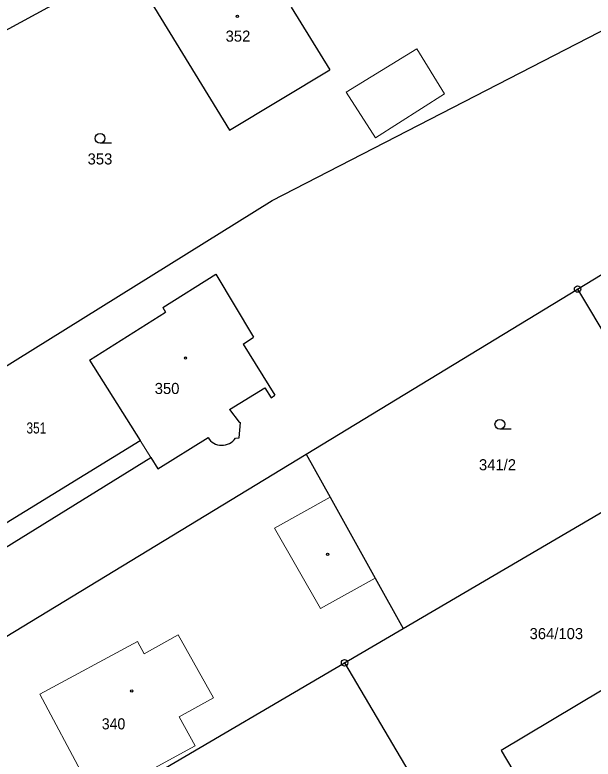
# Model space of a CAD drawing. Extents: x -592965 to -592390, y -1145071 to -1144631.
# Drawn here: x -592638.4 to -592594.1, y -1144937.6 to -1144880.5 of the extents above; entities that cross this region are included whole.
import ezdxf

# ---------------------------------------------------------------- set-up
doc = ezdxf.new("R2010")
doc.units = 0
doc.header["$LTSCALE"] = 0.17
doc.layers.add('4', color=7, linetype='Continuous', lineweight=25)

msp = doc.modelspace()

# ---------------------------------------------------------------- linework, layer by layer
at = {"layer": '4'}
for p, q in [((-592618.69, -1144894.73), (-592582.6, -1144876.15)), ((-592628.45, -1144878.77), (-592621.96, -1144889.35)), ((-592639.79, -1144882.02), (-592635.02, -1144879.44)), ((-592617.24, -1144879.9), (-592614.27, -1144884.71)), ((-592621.96, -1144889.35), (-592614.27, -1144884.71)), ((-592631.025, -1144890.34), (-592631.9, -1144890.34)), ((-592641.03, -1144908.63), (-592618.69, -1144894.73)), ((-592627.1, -1144902.94), (-592623.01, -1144900.39)), ((-592623.01, -1144900.39), (-592620.12, -1144905.2)), ((-592595.26, -1144901.52), (-592587.26, -1144915.04)), ((-592632.71, -1144906.97), (-592626.88, -1144903.29)), ((-592627.1, -1144902.94), (-592626.88, -1144903.29)), ((-592620.93, -1144905.75), (-592620.12, -1144905.2)), ((-592620.93, -1144905.75), (-592618.49, -1144909.67)), ((-592632.71, -1144906.97), (-592628.83, -1144913.14)), ((-592621.97, -1144910.75), (-592619.25, -1144909.11)), ((-592621.97, -1144910.75), (-592621.22, -1144911.74)), ((-592621.22, -1144911.74), (-592621.12, -1144911.75)), ((-592600.355, -1144912.27), (-592601.23, -1144912.27)), ((-592627.47, -1144915.3), (-592623.62, -1144912.91)), ((-592642.54, -1144921.54), (-592628.83, -1144913.14)), ((-592643.64, -1144930.93), (-592616.08, -1144914.18)), ((-592642.78, -1144923.56), (-592628, -1144914.45)), ((-592628, -1144914.45), (-592627.47, -1144915.3)), ((-592616.08, -1144914.18), (-592614.24, -1144917.49)), ((-592614.24, -1144917.49), (-592610.8, -1144923.69)), ((-592613.14, -1144930.18), (-592608.64, -1144927.55)), ((-592636.52, -1144943.86), (-592613.14, -1144930.18))]:
    msp.add_line(p, q, dxfattribs=at)
at = {"layer": '4', "lineweight": 13}
for p, q in [((-592613.01, -1144886.42), (-592607.59, -1144883.1)), ((-592607.59, -1144883.1), (-592605.47, -1144886.56)), ((-592613.01, -1144886.42), (-592610.78, -1144889.93)), ((-592610.78, -1144889.93), (-592605.47, -1144886.56)), ((-592628.83, -1144913.14), (-592628, -1144914.45)), ((-592618.53, -1144919.87), (-592614.24, -1144917.49)), ((-592618.53, -1144919.87), (-592614.99, -1144926.02)), ((-592614.99, -1144926.02), (-592610.8, -1144923.69)), ((-592636.53, -1144932.59), (-592629.03, -1144928.56)), ((-592629.03, -1144928.56), (-592628.51, -1144929.49)), ((-592636.53, -1144932.59), (-592632.22, -1144940.68)), ((-592625.83, -1144934.33), (-592623.21, -1144932.88)), ((-592625.83, -1144934.33), (-592624.61, -1144936.54)), ((-592632.22, -1144940.68), (-592624.61, -1144936.54))]:
    msp.add_line(p, q, dxfattribs=at)
at = {"layer": '4'}
for points in [[(-592616.08, -1144914.18), (-592595.26, -1144901.52), (-592574.92, -1144889.15)], [(-592619.25, -1144909.11), (-592618.77, -1144909.86), (-592618.49, -1144909.67)], [(-592621.52, -1144912.95), (-592621.24, -1144912.94), (-592621.12, -1144911.75)], [(-592610.8, -1144923.69), (-592608.64, -1144927.55), (-592588.13, -1144915.55)], [(-592613.14, -1144930.18), (-592597.16, -1144957.25), (-592596.1, -1144959.04)]]:
    msp.add_lwpolyline(points, dxfattribs=at)
msp.add_lwpolyline([(-592601.13, -1144936.9), (-592597.88, -1144942.39), (-592595.3, -1144940.9), (-592592.02, -1144946.46), (-592584.34, -1144941.94), (-592587.57, -1144936.44), (-592582.29, -1144933.34), (-592585.64, -1144927.65)], close=True, dxfattribs=at)
at = {"layer": '4', "lineweight": 13}
msp.add_lwpolyline([(-592628.51, -1144929.49), (-592625.91, -1144928.03), (-592623.21, -1144932.88)], dxfattribs=at)
at = {"layer": '4'}
for centre, radius in [((-592621.37, -1144880.61), 0.0875), ((-592631.9, -1144889.965), 0.375), ((-592595.26, -1144901.52), 0.25), ((-592595.26, -1144901.52), 0.0164), ((-592625.35, -1144906.81), 0.0875), ((-592601.23, -1144911.895), 0.375), ((-592614.45, -1144921.87), 0.0875), ((-592613.14, -1144930.18), 0.25), ((-592613.14, -1144930.18), 0.0164), ((-592629.47, -1144932.34), 0.0875)]:
    msp.add_circle(centre, radius, dxfattribs=at)
msp.add_arc((-592622.5572, -1144912.2595), 1.2461, 211.47165, 326.34592, dxfattribs=at)

# ---------------------------------------------------------------- texts
for s, p in [('352', (-592622.27, -1144882.55)), ('353', (-592632.86, -1144891.97)), ('350', (-592627.71, -1144909.57)), ('341/2', (-592602.832, -1144915.42)), ('364/103', (-592598.948, -1144928.37))]:
    msp.add_text(s, height=0.85, dxfattribs=at).set_placement(p)
for s, width, p in [('351', 0.8, (-592637.55, -1144912.6)), ('340', 0.95, (-592631.77, -1144935.29))]:
    msp.add_text(s, height=0.85, dxfattribs=dict(at, width=width)).set_placement(p)

doc.saveas('drawing.dxf')
